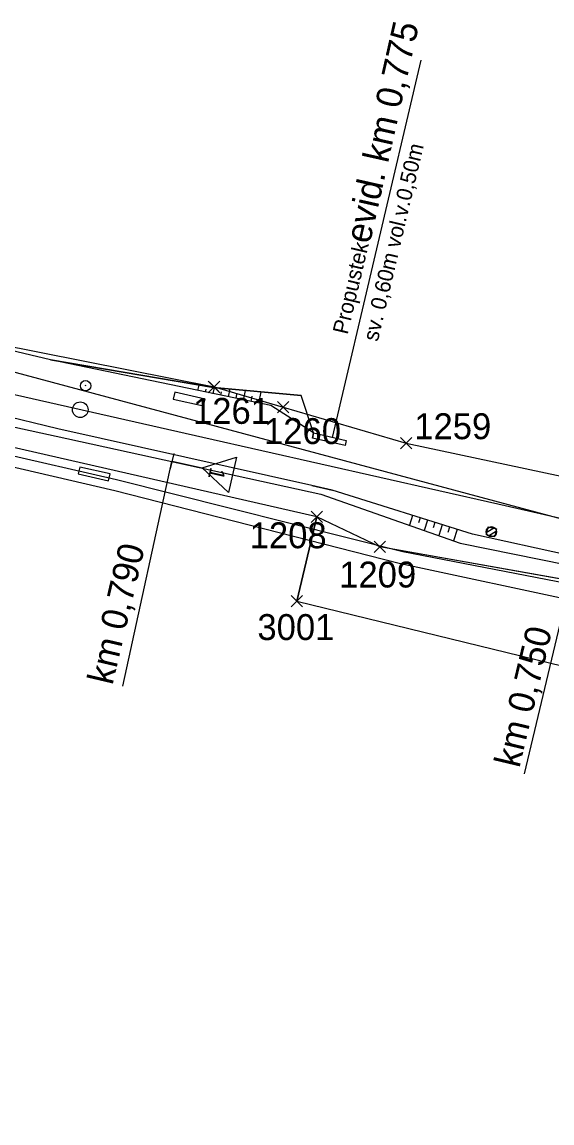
# Model space of a CAD drawing. Extents: x -738085 to -734426, y -1122197 to -1119748.
# Drawn here: x -734776.9 to -734725.8, y -1120253.9 to -1120147.6 of the extents above; entities that cross this region are included whole.
import ezdxf

# ---------------------------------------------------------------- set-up
doc = ezdxf.new("R2010")
doc.units = 0
for name, color, linetype in [('Dočasný zábor - do 1 roku', 7, 'Continuous'), ('SŽDC', 7, 'Continuous'), ('Vrstva 1', 7, 'Continuous'), ('Vrstva 11', 7, 'Continuous'), ('Vrstva 12', 7, 'Continuous'), ('Vrstva 17', 7, 'Continuous'), ('Vrstva 19', 7, 'Continuous'), ('Vrstva 23', 7, 'Continuous'), ('Vrstva 48', 7, 'Continuous'), ('Vrstva 49', 7, 'Continuous'), ('Vrstva 5', 7, 'Continuous'), ('Vrstva 51', 7, 'Continuous'), ('Vrstva 6', 7, 'Continuous'), ('Vrstva 60', 7, 'Continuous'), ('Vrstva 63', 7, 'Continuous'), ('Vrstva 7', 7, 'Continuous')]:
    doc.layers.add(name, color=color, linetype=linetype)

msp = doc.modelspace()

# ---------------------------------------------------------------- linework, layer by layer
at = {"layer": 'Dočasný zábor - do 1 roku'}
for p, q in [((-734750.4, -1120203.56), (-734748.46, -1120195.41)), ((-734748.46, -1120195.41), (-734750.4, -1120203.56)), ((-734742.39, -1120198.31), (-734748.46, -1120195.41)), ((-734750.4, -1120203.56), (-734708.92, -1120213.68))]:
    msp.add_line(p, q, dxfattribs=at)
for points in [[(-734711.94, -1120206.26), (-734711.5, -1120203.79), (-734742.39, -1120198.31)], [(-734750.4, -1120203.56), (-734750.4, -1120203.56)]]:
    msp.add_lwpolyline(points, dxfattribs=at)
at = {"layer": 'SŽDC'}
for p, q in [((-734801.4, -1120174.28), (-734758.4, -1120182.87)), ((-734758.4, -1120182.87), (-734751.71, -1120184.82)), ((-734748.46, -1120195.41), (-734799.69, -1120183.7)), ((-734751.71, -1120184.82), (-734739.85, -1120188.3)), ((-734739.85, -1120188.3), (-734702.73, -1120196.17)), ((-734742.39, -1120198.31), (-734748.46, -1120195.41)), ((-734711.5, -1120203.79), (-734742.39, -1120198.31))]:
    msp.add_line(p, q, dxfattribs=at)
at = {"layer": 'Vrstva 1'}
msp.add_lwpolyline([(-734613.42, -1120220.79), (-734634.89, -1120215.96), (-734653.9, -1120211.66), (-734667.21, -1120208.65), (-734679.78, -1120205.8), (-734683.65, -1120204.92), (-734685.4, -1120204.52), (-734700.12, -1120201.2), (-734707.73, -1120199.48), (-734730.99, -1120194.2), (-734759.47, -1120187.75), (-734794.9, -1120179.75), (-734825.42, -1120172.84), (-734846.46, -1120168.09), (-734858.48, -1120165.34)], dxfattribs=at)
msp.add_lwpolyline([(-734613.42, -1120220.79), (-734634.89, -1120215.96), (-734653.9, -1120211.66), (-734667.21, -1120208.65), (-734679.78, -1120205.8), (-734683.65, -1120204.92), (-734685.4, -1120204.52), (-734700.12, -1120201.2), (-734707.73, -1120199.48), (-734730.99, -1120194.2), (-734759.47, -1120187.75), (-734794.9, -1120179.75), (-734825.42, -1120172.84), (-734846.46, -1120168.09), (-734858.48, -1120165.34)], dxfattribs=at)
at = {"layer": 'Vrstva 11'}
for p, q in [((-734731.31, -1120196.46), (-734732.1, -1120196.95)), ((-734731.12, -1120196.78), (-734731.89, -1120197.26))]:
    msp.add_line(p, q, dxfattribs=at)
msp.add_circle((-734731.61, -1120196.85), 0.5, dxfattribs=at)
at = {"layer": 'Vrstva 12'}
msp.add_lwpolyline([(-734731.91, -1120196.38), (-734731.13, -1120196.55), (-734731.31, -1120197.33), (-734732.09, -1120197.16), (-734731.91, -1120196.38)], dxfattribs=at)
at = {"layer": 'Vrstva 17'}
msp.add_lwpolyline([(-734749.98, -1120183.69), (-734758.44, -1120182.92), (-734774.19, -1120180.25), (-734801.33, -1120173.81), (-734866.4, -1120157.58), (-734890.66, -1120155.06), (-734909.69, -1120153.67), (-734921.82, -1120153.78), (-734933.01, -1120154.69)], dxfattribs=at)
at = {"layer": 'Vrstva 19'}
for p, q in [((-734746.94, -1120187.74), (-734738.39, -1120151.31)), ((-734748.79, -1120187.31), (-734745.63, -1120188.05)), ((-734748.94, -1120192.38), (-734747, -1120192.82))]:
    msp.add_line(p, q, dxfattribs=at)
for points in [[(-734748.79, -1120187.31), (-734748.79, -1120187.31), (-734748.88, -1120187.82)], [(-734745.72, -1120188.53), (-734748.88, -1120187.82), (-734748.79, -1120187.31), (-734745.63, -1120188.05), (-734745.72, -1120188.53)], [(-734745.72, -1120188.53), (-734748.88, -1120187.82), (-734748.79, -1120187.31), (-734745.63, -1120188.05), (-734745.72, -1120188.53)], [(-734745.63, -1120188.05), (-734745.63, -1120188.05), (-734745.72, -1120188.53)]]:
    msp.add_lwpolyline(points, dxfattribs=at)
at = {"layer": 'Vrstva 23'}
for points in [[(-734759.42, -1120184.7), (-734759.27, -1120184.04), (-734762.19, -1120183.38), (-734762.34, -1120184.04)], [(-734768.59, -1120191.92), (-734768.44, -1120191.26), (-734771.37, -1120190.6), (-734771.51, -1120191.26)]]:
    msp.add_lwpolyline(points, close=True, dxfattribs=at)
at = {"layer": 'Vrstva 48'}
for p, q in [((-734759.95, -1120183.21), (-734759.84, -1120182.68)), ((-734758.48, -1120183.52), (-734758.35, -1120182.92)), ((-734757.01, -1120183.82), (-734756.85, -1120183.06)), ((-734759.21, -1120183.36), (-734759.15, -1120183.08)), ((-734757.74, -1120183.67), (-734757.67, -1120183.33)), ((-734756.27, -1120183.97), (-734756.19, -1120183.55)), ((-734755.54, -1120184.13), (-734755.35, -1120183.2)), ((-734754.81, -1120184.28), (-734754.7, -1120183.77)), ((-734754.07, -1120184.43), (-734753.84, -1120183.34)), ((-734739.22, -1120195.27), (-734739.52, -1120196.22)), ((-734738.5, -1120195.49), (-734738.66, -1120195.98)), ((-734737.79, -1120195.72), (-734738.1, -1120196.72)), ((-734737.07, -1120195.95), (-734737.23, -1120196.46)), ((-734736.36, -1120196.17), (-734736.69, -1120197.22)), ((-734735.64, -1120196.4), (-734735.81, -1120196.93)), ((-734734.93, -1120196.62), (-734735.27, -1120197.71))]:
    msp.add_line(p, q, dxfattribs=at)
at = {"layer": 'Vrstva 49'}
for p, q in [((-734767.83, -1120191.85), (-734818.33, -1120180.21)), ((-734773.48, -1120186.9), (-734801.95, -1120180.12)), ((-734748.94, -1120192.38), (-734773.48, -1120186.9)), ((-734740.17, -1120198.78), (-734767.83, -1120191.85)), ((-734747, -1120192.82), (-734748.94, -1120192.38)), ((-734733.43, -1120197.09), (-734747, -1120192.82)), ((-734724.05, -1120199.13), (-734733.43, -1120197.09)), ((-734722.1, -1120202.28), (-734740.17, -1120198.78))]:
    msp.add_line(p, q, dxfattribs=at)
for points in [[(-735120.53, -1120253.93), (-735071.24, -1120223.86), (-735031.45, -1120200.68), (-735001.39, -1120183.23), (-734979.37, -1120173.86), (-734964.99, -1120169.04), (-734946.77, -1120164.63), (-734926.51, -1120162.42), (-734904.58, -1120162.2), (-734885.6, -1120163.73), (-734860.45, -1120168.24), (-734808.17, -1120179.8), (-734802.31, -1120181.01), (-734795.9, -1120182.78), (-734795.12, -1120182.96), (-734773.64, -1120187.62), (-734748.07, -1120193.22), (-734734.64, -1120197.94), (-734724.28, -1120200.04), (-734701.99, -1120203.61), (-734701.41, -1120203.78)], [(-734774.19, -1120180.25), (-734758.44, -1120182.92), (-734749.98, -1120183.69)], [(-734748.79, -1120187.31), (-734752.91, -1120184.67), (-734774.19, -1120180.25)], [(-734748.79, -1120187.31), (-734748.79, -1120187.31), (-734749.98, -1120183.69)]]:
    msp.add_lwpolyline(points, dxfattribs=at)
at = {"layer": 'Vrstva 5'}
for p, q in [((-734762.29, -1120189.3), (-734762.62, -1120190.76)), ((-734767.21, -1120211.74), (-734762.46, -1120190.07))]:
    msp.add_line(p, q, dxfattribs=at)
msp.add_lwpolyline([(-734762.45, -1120190.03), (-734759.53, -1120190.69), (-734756.22, -1120189.65), (-734756.99, -1120193.06), (-734759.53, -1120190.69)], dxfattribs=at)
at = {"layer": 'Vrstva 51'}
msp.add_lwpolyline([(-734722.77, -1120203.71), (-734740.51, -1120199.91), (-734767.99, -1120192.9), (-734818.44, -1120181.19), (-734836.45, -1120178), (-734844.24, -1120177.16), (-734859.66, -1120177.39)], dxfattribs=at)
at = {"layer": 'Vrstva 6'}
msp.add_line((-734723.34, -1120198.74), (-734728.45, -1120220.22), dxfattribs=at)
at = {"layer": 'Vrstva 60'}
for p, q in [((-734757.95, -1120183.32), (-734758.95, -1120182.32)), ((-734757.95, -1120182.42), (-734758.95, -1120183.42)), ((-734758.85, -1120183.32), (-734757.85, -1120182.32)), ((-734758.85, -1120182.42), (-734757.85, -1120183.42)), ((-734758.4, -1120182.87), (-734758.4, -1120182.87)), ((-734751.26, -1120185.27), (-734752.26, -1120184.27)), ((-734751.26, -1120184.37), (-734752.26, -1120185.37)), ((-734752.16, -1120185.27), (-734751.16, -1120184.27)), ((-734752.16, -1120184.37), (-734751.16, -1120185.37)), ((-734751.71, -1120184.82), (-734751.71, -1120184.82)), ((-734739.4, -1120188.75), (-734740.4, -1120187.75)), ((-734739.4, -1120187.85), (-734740.4, -1120188.85)), ((-734740.3, -1120188.75), (-734739.3, -1120187.75)), ((-734740.3, -1120187.85), (-734739.3, -1120188.85)), ((-734739.85, -1120188.3), (-734739.85, -1120188.3)), ((-734748.01, -1120195.86), (-734749.01, -1120194.86)), ((-734748.01, -1120194.96), (-734749.01, -1120195.96)), ((-734748.91, -1120195.86), (-734747.91, -1120194.86)), ((-734748.91, -1120194.96), (-734747.91, -1120195.96)), ((-734748.46, -1120195.41), (-734748.46, -1120195.41)), ((-734741.94, -1120198.76), (-734742.94, -1120197.76)), ((-734741.94, -1120197.86), (-734742.94, -1120198.86)), ((-734742.84, -1120198.76), (-734741.84, -1120197.76)), ((-734742.84, -1120197.86), (-734741.84, -1120198.86)), ((-734742.39, -1120198.31), (-734742.39, -1120198.31)), ((-734749.95, -1120204.01), (-734750.95, -1120203.01)), ((-734749.95, -1120203.11), (-734750.95, -1120204.11)), ((-734750.85, -1120204.01), (-734749.85, -1120203.01)), ((-734750.85, -1120203.11), (-734749.85, -1120204.11)), ((-734750.4, -1120203.56), (-734750.4, -1120203.56))]:
    msp.add_line(p, q, dxfattribs=at)
at = {"layer": 'Vrstva 63'}
msp.add_line((-734784.59, -1120179.58), (-734667.47, -1120210.99), dxfattribs=at)
at = {"layer": 'Vrstva 7'}
msp.add_line((-734770.75, -1120182.76), (-734770.85, -1120182.74), dxfattribs=at)
for centre, radius in [((-734770.8, -1120182.75), 0.5), ((-734771.32, -1120185.07), 0.75), ((-734771.32, -1120185.07), 0.75)]:
    msp.add_circle(centre, radius, dxfattribs=at)

# ---------------------------------------------------------------- texts
at = {"layer": 'Vrstva 19'}
for s, height, rotation, p in [('evid. km 0,775', 2.5, 77.358, (-734743.35, -1120169.13)), ('sv. 0,60m vol.v.0,50m', 1.5, 76.8099, (-734742.58, -1120178.55)), ('Propustek', 1.5, 76.8099, (-734745.5, -1120177.87))]:
    msp.add_text(s, height=height, rotation=rotation, dxfattribs=at).set_placement(p)
at = {"layer": 'Vrstva 5'}
for s, height, rotation, p in [('1', 1.5, 257.2679, (-734758.73, -1120190.55)), ('km 0,790', 2.5, 76.7843, (-734768.21, -1120211.72))]:
    msp.add_text(s, height=height, rotation=rotation, dxfattribs=at).set_placement(p)
at = {"layer": 'Vrstva 6'}
msp.add_text('km 0,750', height=2.5, rotation=76.6206, dxfattribs=at).set_placement((-734728.91, -1120219.72))
at = {"layer": 'Vrstva 60'}
for s, p in [('1261', (-734760.43, -1120186.43)), ('1260', (-734753.57, -1120188.38)), ('1259', (-734739.06, -1120187.91)), ('1208', (-734754.96, -1120198.44)), ('1209', (-734746.31, -1120202.23)), ('3001', (-734754.21, -1120207.3))]:
    msp.add_text(s, height=2.5, dxfattribs=at).set_placement(p)

doc.saveas('drawing.dxf')
